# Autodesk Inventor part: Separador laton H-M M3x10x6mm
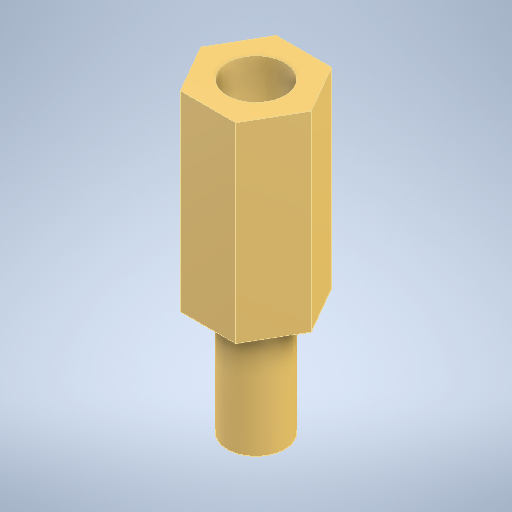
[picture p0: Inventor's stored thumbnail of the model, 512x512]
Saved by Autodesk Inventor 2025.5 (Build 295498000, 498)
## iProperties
Created: 2018-08
Part Number: Separador laton H-M M3x10x6mm
Material: solidworks materials|Latón
Document SubType Name: Modeling
Designer: Luis M
Density: 8.5 g/cm^3
Appearance: polished brass
Sending System: SolidWorks 2017
Last Author: Jonathan
Last Saved: 2018-08-15
Author: Luis M
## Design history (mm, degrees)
feature "Saliente-Extruir1"
feature "Saliente-Extruir2"
node "Sólido1"
node "Sólido2"
